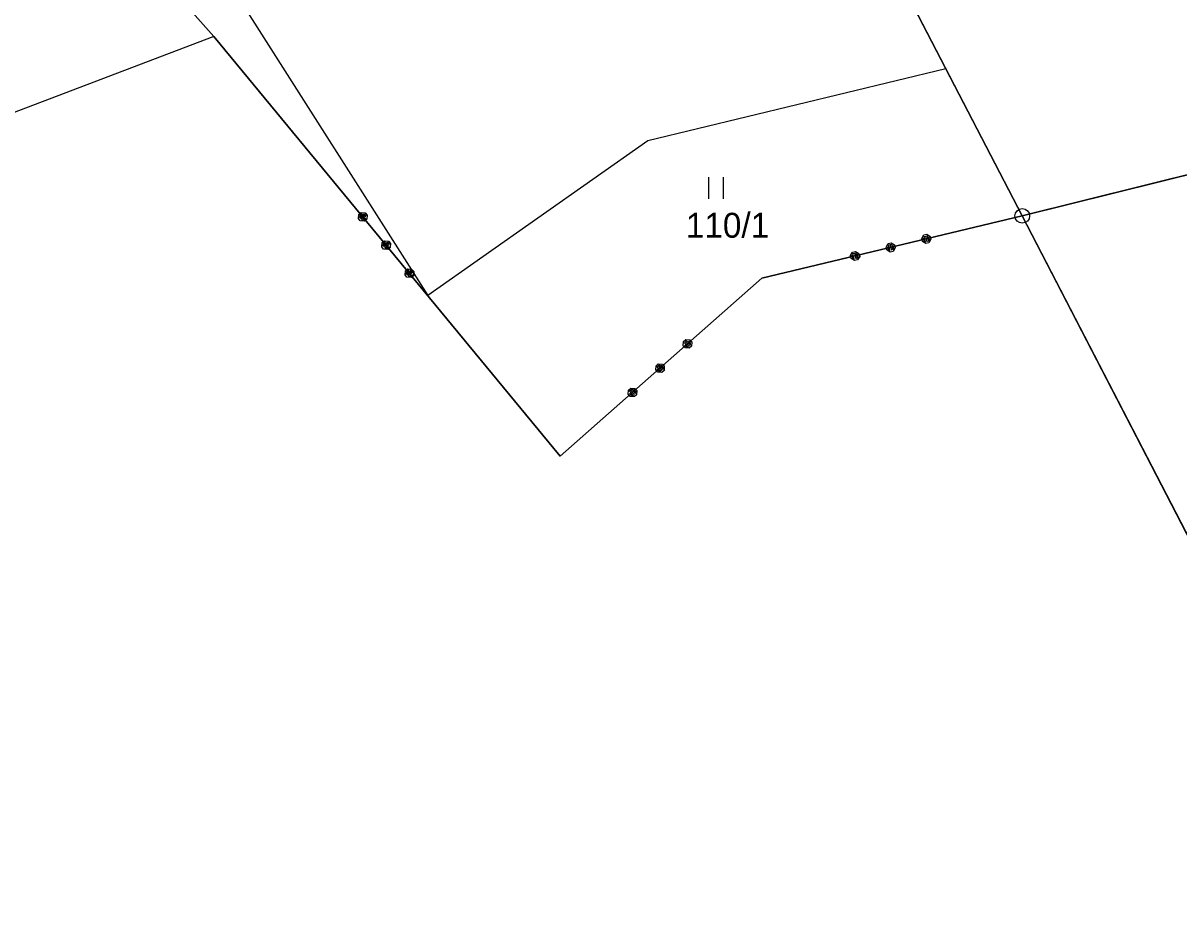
# Model space of a CAD drawing. Extents: x -866656 to -858817, y -1041816 to -1038653.
# Drawn here: x -865090.2 to -865011.3, y -1040747.1 to -1040686 of the extents above; entities that cross this region are included whole.
import ezdxf

# ---------------------------------------------------------------- set-up
doc = ezdxf.new("R2010")
doc.units = 0
for name, color, linetype in [('SZDC', 7, 'Continuous'), ('Vrstva 1', 7, 'Continuous'), ('Vrstva 3', 7, 'Continuous'), ('Vrstva 53', 7, 'Continuous')]:
    doc.layers.add(name, color=color, linetype=linetype)

msp = doc.modelspace()

# ---------------------------------------------------------------- linework, layer by layer
at = {"layer": 'SZDC'}
for points in [[(-865001.396, -1040539.962), (-864993.688, -1040579.203), (-864996.501, -1040608.857), (-865002.06, -1040629.39), (-864985.688, -1040660.423), (-864988.738, -1040690.926), (-865021.96, -1040699.19), (-865027.168, -1040689.139), (-865033.06, -1040677.767), (-865026.63, -1040662), (-865024.654, -1040657.157), (-865013.46, -1040629.71), (-865015.641, -1040623.593), (-865021.207, -1040607.979), (-865022.973, -1040591.404), (-865024.6, -1040576.14), (-865021.44, -1040540.27)], [(-864972.331, -1040948.544), (-864965.463, -1040904.572), (-864985, -1040866.09), (-864987.66, -1040820.56), (-865008.38, -1040725.45), (-865021.96, -1040699.19), (-864988.738, -1040690.926), (-864994.191, -1040709.967), (-864984.36, -1040712.09), (-864979.245, -1040734.883), (-864978.161, -1040739.712), (-864978.755, -1040767.78), (-864956.64, -1040823.78), (-864971.416, -1040839.192), (-864953.61, -1040862.72), (-864958.96, -1040864.07), (-864953.81, -1040886.99), (-864953.18, -1040911.04), (-864934.86, -1040933.14), (-864931.196, -1040972.036)]]:
    msp.add_lwpolyline(points, dxfattribs=at)
at = {"layer": 'Vrstva 1'}
for p, q in [((-865080.1, -1040677.003), (-865062.538, -1040704.629)), ((-865033.06, -1040677.767), (-865021.96, -1040699.19)), ((-865077.15, -1040686.93), (-865106.09, -1040697.94)), ((-865027.168, -1040689.139), (-865047.517, -1040694.061)), ((-865047.517, -1040694.061), (-865062.538, -1040704.629)), ((-865043.383, -1040696.532), (-865043.383, -1040698.032)), ((-865042.383, -1040696.532), (-865042.383, -1040698.032)), ((-865021.96, -1040699.19), (-865008.38, -1040725.45))]:
    msp.add_line(p, q, dxfattribs=at)
for radius in [0.5, 0.01]:
    msp.add_circle((-865021.96, -1040699.19), radius, dxfattribs=at)
at = {"layer": 'Vrstva 3'}
for p, q in [((-865084.06, -1040679.12), (-865077.15, -1040686.93)), ((-865077.15, -1040686.93), (-865084.06, -1040679.12)), ((-865077.15, -1040686.93), (-865053.49, -1040715.59)), ((-865053.49, -1040715.59), (-865077.15, -1040686.93)), ((-865021.96, -1040699.19), (-864988.738, -1040690.926)), ((-864988.738, -1040690.926), (-865021.96, -1040699.19)), ((-865067.27, -1040699.368), (-865067.243, -1040699.087)), ((-865067.27, -1040699.368), (-865067.243, -1040699.087)), ((-865067.142, -1040699.523), (-865067.27, -1040699.368)), ((-865067.142, -1040699.523), (-865067.27, -1040699.368)), ((-865067.243, -1040699.087), (-865067.089, -1040698.959)), ((-865067.243, -1040699.087), (-865067.089, -1040698.959)), ((-865067.193, -1040699.305), (-865066.884, -1040699.05)), ((-865067.193, -1040699.305), (-865066.884, -1040699.05)), ((-865067.179, -1040699.164), (-865067.193, -1040699.305)), ((-865067.179, -1040699.164), (-865067.193, -1040699.305)), ((-865067.025, -1040699.037), (-865067.179, -1040699.164)), ((-865067.025, -1040699.037), (-865067.179, -1040699.164)), ((-865066.861, -1040699.549), (-865067.142, -1040699.523)), ((-865066.861, -1040699.549), (-865067.142, -1040699.523)), ((-865066.821, -1040699.127), (-865067.129, -1040699.382)), ((-865066.821, -1040699.127), (-865067.129, -1040699.382)), ((-865067.089, -1040698.959), (-865066.807, -1040698.986)), ((-865067.089, -1040698.959), (-865066.807, -1040698.986)), ((-865066.757, -1040699.204), (-865067.065, -1040699.459)), ((-865066.757, -1040699.204), (-865067.065, -1040699.459)), ((-865067.065, -1040699.459), (-865066.925, -1040699.472)), ((-865067.065, -1040699.459), (-865066.925, -1040699.472)), ((-865066.925, -1040699.472), (-865066.77, -1040699.345)), ((-865066.925, -1040699.472), (-865066.77, -1040699.345)), ((-865066.884, -1040699.05), (-865066.757, -1040699.204)), ((-865066.884, -1040699.05), (-865066.757, -1040699.204)), ((-865066.707, -1040699.422), (-865066.861, -1040699.549)), ((-865066.707, -1040699.422), (-865066.861, -1040699.549)), ((-865066.807, -1040698.986), (-865066.68, -1040699.141)), ((-865066.807, -1040698.986), (-865066.68, -1040699.141)), ((-865066.68, -1040699.141), (-865066.707, -1040699.422)), ((-865066.68, -1040699.141), (-865066.707, -1040699.422)), ((-865039.73, -1040703.45), (-865021.96, -1040699.19)), ((-865021.96, -1040699.19), (-865039.73, -1040703.45)), ((-865028.826, -1040700.733), (-865028.678, -1040700.492)), ((-865028.826, -1040700.733), (-865028.678, -1040700.492)), ((-865028.678, -1040700.492), (-865028.483, -1040700.445)), ((-865028.678, -1040700.492), (-865028.483, -1040700.445)), ((-865028.483, -1040700.445), (-865028.242, -1040700.593)), ((-865028.483, -1040700.445), (-865028.242, -1040700.593)), ((-865065.678, -1040701.296), (-865065.651, -1040701.015)), ((-865065.678, -1040701.296), (-865065.651, -1040701.015)), ((-865065.651, -1040701.015), (-865065.497, -1040700.887)), ((-865065.651, -1040701.015), (-865065.497, -1040700.887)), ((-865065.601, -1040701.233), (-865065.293, -1040700.978)), ((-865065.601, -1040701.233), (-865065.293, -1040700.978)), ((-865065.588, -1040701.092), (-865065.601, -1040701.233)), ((-865065.588, -1040701.092), (-865065.601, -1040701.233)), ((-865065.433, -1040700.964), (-865065.588, -1040701.092)), ((-865065.433, -1040700.964), (-865065.588, -1040701.092)), ((-865065.229, -1040701.055), (-865065.537, -1040701.31)), ((-865065.229, -1040701.055), (-865065.537, -1040701.31)), ((-865065.497, -1040700.887), (-865065.215, -1040700.914)), ((-865065.497, -1040700.887), (-865065.215, -1040700.914)), ((-865065.165, -1040701.132), (-865065.474, -1040701.387)), ((-865065.165, -1040701.132), (-865065.474, -1040701.387)), ((-865065.333, -1040701.4), (-865065.179, -1040701.273)), ((-865065.333, -1040701.4), (-865065.179, -1040701.273)), ((-865065.293, -1040700.978), (-865065.165, -1040701.132)), ((-865065.293, -1040700.978), (-865065.165, -1040701.132)), ((-865065.215, -1040700.914), (-865065.088, -1040701.069)), ((-865065.215, -1040700.914), (-865065.088, -1040701.069)), ((-865065.088, -1040701.069), (-865065.115, -1040701.35)), ((-865065.088, -1040701.069), (-865065.115, -1040701.35)), ((-865031.257, -1040701.316), (-865031.109, -1040701.074)), ((-865031.257, -1040701.316), (-865031.109, -1040701.074)), ((-865031.16, -1040701.292), (-865031.113, -1040701.487)), ((-865031.16, -1040701.292), (-865031.113, -1040701.487)), ((-865031.109, -1040701.074), (-865030.914, -1040701.028)), ((-865031.109, -1040701.074), (-865030.914, -1040701.028)), ((-865031.086, -1040701.172), (-865030.891, -1040701.125)), ((-865031.086, -1040701.172), (-865030.891, -1040701.125)), ((-865030.992, -1040701.561), (-865031.086, -1040701.172)), ((-865030.992, -1040701.561), (-865031.086, -1040701.172)), ((-865030.988, -1040701.148), (-865030.895, -1040701.537)), ((-865030.988, -1040701.148), (-865030.895, -1040701.537)), ((-865030.914, -1040701.028), (-865030.673, -1040701.176)), ((-865030.914, -1040701.028), (-865030.673, -1040701.176)), ((-865030.891, -1040701.125), (-865030.798, -1040701.514)), ((-865030.891, -1040701.125), (-865030.798, -1040701.514)), ((-865030.724, -1040701.393), (-865030.771, -1040701.199)), ((-865030.724, -1040701.393), (-865030.771, -1040701.199)), ((-865030.673, -1040701.176), (-865030.627, -1040701.37)), ((-865030.673, -1040701.176), (-865030.627, -1040701.37)), ((-865028.779, -1040700.927), (-865028.826, -1040700.733)), ((-865028.779, -1040700.927), (-865028.826, -1040700.733)), ((-865028.538, -1040701.075), (-865028.779, -1040700.927)), ((-865028.538, -1040701.075), (-865028.779, -1040700.927)), ((-865028.728, -1040700.709), (-865028.682, -1040700.904)), ((-865028.728, -1040700.709), (-865028.682, -1040700.904)), ((-865028.682, -1040700.904), (-865028.561, -1040700.978)), ((-865028.682, -1040700.904), (-865028.561, -1040700.978)), ((-865028.655, -1040700.589), (-865028.46, -1040700.542)), ((-865028.655, -1040700.589), (-865028.46, -1040700.542)), ((-865028.561, -1040700.978), (-865028.655, -1040700.589)), ((-865028.561, -1040700.978), (-865028.655, -1040700.589)), ((-865028.557, -1040700.566), (-865028.464, -1040700.955)), ((-865028.557, -1040700.566), (-865028.464, -1040700.955)), ((-865028.343, -1040701.028), (-865028.538, -1040701.075)), ((-865028.343, -1040701.028), (-865028.538, -1040701.075)), ((-865028.46, -1040700.542), (-865028.367, -1040700.931)), ((-865028.46, -1040700.542), (-865028.367, -1040700.931)), ((-865028.367, -1040700.931), (-865028.293, -1040700.811)), ((-865028.367, -1040700.931), (-865028.293, -1040700.811)), ((-865028.196, -1040700.787), (-865028.343, -1040701.028)), ((-865028.196, -1040700.787), (-865028.343, -1040701.028)), ((-865028.293, -1040700.811), (-865028.339, -1040700.616)), ((-865028.293, -1040700.811), (-865028.339, -1040700.616)), ((-865028.242, -1040700.593), (-865028.196, -1040700.787)), ((-865028.242, -1040700.593), (-865028.196, -1040700.787)), ((-865065.551, -1040701.45), (-865065.678, -1040701.296)), ((-865065.551, -1040701.45), (-865065.678, -1040701.296)), ((-865065.269, -1040701.477), (-865065.551, -1040701.45)), ((-865065.269, -1040701.477), (-865065.551, -1040701.45)), ((-865065.474, -1040701.387), (-865065.333, -1040701.4)), ((-865065.474, -1040701.387), (-865065.333, -1040701.4)), ((-865065.115, -1040701.35), (-865065.269, -1040701.477)), ((-865065.115, -1040701.35), (-865065.269, -1040701.477)), ((-865033.688, -1040701.898), (-865033.54, -1040701.657)), ((-865033.688, -1040701.898), (-865033.54, -1040701.657)), ((-865033.641, -1040702.093), (-865033.688, -1040701.898)), ((-865033.641, -1040702.093), (-865033.688, -1040701.898)), ((-865033.591, -1040701.875), (-865033.544, -1040702.07)), ((-865033.591, -1040701.875), (-865033.544, -1040702.07)), ((-865033.544, -1040702.07), (-865033.423, -1040702.143)), ((-865033.544, -1040702.07), (-865033.423, -1040702.143)), ((-865033.54, -1040701.657), (-865033.346, -1040701.611)), ((-865033.54, -1040701.657), (-865033.346, -1040701.611)), ((-865033.517, -1040701.754), (-865033.322, -1040701.708)), ((-865033.517, -1040701.754), (-865033.322, -1040701.708)), ((-865033.423, -1040702.143), (-865033.517, -1040701.754)), ((-865033.423, -1040702.143), (-865033.517, -1040701.754)), ((-865033.419, -1040701.731), (-865033.326, -1040702.12)), ((-865033.419, -1040701.731), (-865033.326, -1040702.12)), ((-865033.346, -1040701.611), (-865033.104, -1040701.758)), ((-865033.346, -1040701.611), (-865033.104, -1040701.758)), ((-865033.322, -1040701.708), (-865033.229, -1040702.097)), ((-865033.322, -1040701.708), (-865033.229, -1040702.097)), ((-865033.229, -1040702.097), (-865033.155, -1040701.976)), ((-865033.229, -1040702.097), (-865033.155, -1040701.976)), ((-865033.058, -1040701.953), (-865033.206, -1040702.194)), ((-865033.058, -1040701.953), (-865033.206, -1040702.194)), ((-865033.155, -1040701.976), (-865033.202, -1040701.782)), ((-865033.155, -1040701.976), (-865033.202, -1040701.782)), ((-865033.104, -1040701.758), (-865033.058, -1040701.953)), ((-865033.104, -1040701.758), (-865033.058, -1040701.953)), ((-865031.21, -1040701.51), (-865031.257, -1040701.316)), ((-865031.21, -1040701.51), (-865031.257, -1040701.316)), ((-865030.969, -1040701.658), (-865031.21, -1040701.51)), ((-865030.969, -1040701.658), (-865031.21, -1040701.51)), ((-865031.113, -1040701.487), (-865030.992, -1040701.561)), ((-865031.113, -1040701.487), (-865030.992, -1040701.561)), ((-865030.775, -1040701.611), (-865030.969, -1040701.658)), ((-865030.775, -1040701.611), (-865030.969, -1040701.658)), ((-865030.798, -1040701.514), (-865030.724, -1040701.393)), ((-865030.798, -1040701.514), (-865030.724, -1040701.393)), ((-865030.627, -1040701.37), (-865030.775, -1040701.611)), ((-865030.627, -1040701.37), (-865030.775, -1040701.611)), ((-865064.06, -1040702.943), (-865063.905, -1040702.815)), ((-865064.06, -1040702.943), (-865063.905, -1040702.815)), ((-865063.905, -1040702.815), (-865063.624, -1040702.842)), ((-865063.905, -1040702.815), (-865063.624, -1040702.842)), ((-865063.624, -1040702.842), (-865063.497, -1040702.996)), ((-865063.624, -1040702.842), (-865063.497, -1040702.996)), ((-865033.4, -1040702.241), (-865033.641, -1040702.093)), ((-865033.4, -1040702.241), (-865033.641, -1040702.093)), ((-865033.206, -1040702.194), (-865033.4, -1040702.241)), ((-865033.206, -1040702.194), (-865033.4, -1040702.241)), ((-865064.087, -1040703.224), (-865064.06, -1040702.943)), ((-865064.087, -1040703.224), (-865064.06, -1040702.943)), ((-865063.959, -1040703.378), (-865064.087, -1040703.224)), ((-865063.959, -1040703.378), (-865064.087, -1040703.224)), ((-865064.009, -1040703.161), (-865063.701, -1040702.906)), ((-865064.009, -1040703.161), (-865063.701, -1040702.906)), ((-865063.996, -1040703.02), (-865064.009, -1040703.161)), ((-865063.996, -1040703.02), (-865064.009, -1040703.161)), ((-865063.842, -1040702.892), (-865063.996, -1040703.02)), ((-865063.842, -1040702.892), (-865063.996, -1040703.02)), ((-865063.678, -1040703.405), (-865063.959, -1040703.378)), ((-865063.678, -1040703.405), (-865063.959, -1040703.378)), ((-865063.637, -1040702.983), (-865063.946, -1040703.238)), ((-865063.637, -1040702.983), (-865063.946, -1040703.238)), ((-865063.574, -1040703.06), (-865063.882, -1040703.315)), ((-865063.574, -1040703.06), (-865063.882, -1040703.315)), ((-865063.882, -1040703.315), (-865063.741, -1040703.328)), ((-865063.882, -1040703.315), (-865063.741, -1040703.328)), ((-865063.741, -1040703.328), (-865063.587, -1040703.201)), ((-865063.741, -1040703.328), (-865063.587, -1040703.201)), ((-865063.701, -1040702.906), (-865063.574, -1040703.06)), ((-865063.701, -1040702.906), (-865063.574, -1040703.06)), ((-865063.523, -1040703.278), (-865063.678, -1040703.405)), ((-865063.523, -1040703.278), (-865063.678, -1040703.405)), ((-865063.497, -1040702.996), (-865063.523, -1040703.278)), ((-865063.497, -1040702.996), (-865063.523, -1040703.278)), ((-865053.49, -1040715.59), (-865039.73, -1040703.45)), ((-865039.73, -1040703.45), (-865053.49, -1040715.59)), ((-865045.101, -1040708.055), (-865045.083, -1040707.773)), ((-865045.101, -1040708.055), (-865045.083, -1040707.773)), ((-865044.969, -1040708.205), (-865045.101, -1040708.055)), ((-865044.969, -1040708.205), (-865045.101, -1040708.055)), ((-865045.083, -1040707.773), (-865044.933, -1040707.641)), ((-865045.083, -1040707.773), (-865044.933, -1040707.641)), ((-865045.026, -1040707.989), (-865044.894, -1040708.139)), ((-865045.026, -1040707.989), (-865044.894, -1040708.139)), ((-865045.017, -1040707.848), (-865044.867, -1040707.716)), ((-865045.017, -1040707.848), (-865044.867, -1040707.716)), ((-865044.752, -1040708.148), (-865045.017, -1040707.848)), ((-865044.752, -1040708.148), (-865045.017, -1040707.848)), ((-865044.686, -1040708.223), (-865044.969, -1040708.205)), ((-865044.686, -1040708.223), (-865044.969, -1040708.205)), ((-865044.942, -1040707.782), (-865044.678, -1040708.082)), ((-865044.942, -1040707.782), (-865044.678, -1040708.082)), ((-865044.933, -1040707.641), (-865044.651, -1040707.658)), ((-865044.933, -1040707.641), (-865044.651, -1040707.658)), ((-865044.894, -1040708.139), (-865044.752, -1040708.148)), ((-865044.894, -1040708.139), (-865044.752, -1040708.148)), ((-865044.867, -1040707.716), (-865044.603, -1040708.016)), ((-865044.867, -1040707.716), (-865044.603, -1040708.016)), ((-865044.594, -1040707.874), (-865044.726, -1040707.724)), ((-865044.594, -1040707.874), (-865044.726, -1040707.724)), ((-865044.536, -1040708.091), (-865044.686, -1040708.223)), ((-865044.536, -1040708.091), (-865044.686, -1040708.223)), ((-865044.651, -1040707.658), (-865044.519, -1040707.808)), ((-865044.651, -1040707.658), (-865044.519, -1040707.808)), ((-865044.603, -1040708.016), (-865044.594, -1040707.874)), ((-865044.603, -1040708.016), (-865044.594, -1040707.874)), ((-865044.519, -1040707.808), (-865044.536, -1040708.091)), ((-865044.519, -1040707.808), (-865044.536, -1040708.091)), ((-865046.976, -1040709.709), (-865046.958, -1040709.427)), ((-865046.976, -1040709.709), (-865046.958, -1040709.427)), ((-865046.843, -1040709.859), (-865046.976, -1040709.709)), ((-865046.843, -1040709.859), (-865046.976, -1040709.709)), ((-865046.958, -1040709.427), (-865046.808, -1040709.295)), ((-865046.958, -1040709.427), (-865046.808, -1040709.295)), ((-865046.901, -1040709.643), (-865046.768, -1040709.793)), ((-865046.901, -1040709.643), (-865046.768, -1040709.793)), ((-865046.892, -1040709.502), (-865046.742, -1040709.37)), ((-865046.892, -1040709.502), (-865046.742, -1040709.37)), ((-865046.627, -1040709.802), (-865046.892, -1040709.502)), ((-865046.627, -1040709.802), (-865046.892, -1040709.502)), ((-865046.561, -1040709.877), (-865046.843, -1040709.859)), ((-865046.561, -1040709.877), (-865046.843, -1040709.859)), ((-865046.817, -1040709.436), (-865046.552, -1040709.736)), ((-865046.817, -1040709.436), (-865046.552, -1040709.736)), ((-865046.808, -1040709.295), (-865046.526, -1040709.312)), ((-865046.808, -1040709.295), (-865046.526, -1040709.312)), ((-865046.768, -1040709.793), (-865046.627, -1040709.802)), ((-865046.768, -1040709.793), (-865046.627, -1040709.802)), ((-865046.742, -1040709.37), (-865046.477, -1040709.669)), ((-865046.742, -1040709.37), (-865046.477, -1040709.669)), ((-865046.468, -1040709.528), (-865046.601, -1040709.378)), ((-865046.468, -1040709.528), (-865046.601, -1040709.378)), ((-865046.411, -1040709.744), (-865046.561, -1040709.877)), ((-865046.411, -1040709.744), (-865046.561, -1040709.877)), ((-865046.526, -1040709.312), (-865046.393, -1040709.462)), ((-865046.526, -1040709.312), (-865046.393, -1040709.462)), ((-865046.477, -1040709.669), (-865046.468, -1040709.528)), ((-865046.477, -1040709.669), (-865046.468, -1040709.528)), ((-865046.393, -1040709.462), (-865046.411, -1040709.744)), ((-865046.393, -1040709.462), (-865046.411, -1040709.744)), ((-865048.85, -1040711.363), (-865048.833, -1040711.081)), ((-865048.85, -1040711.363), (-865048.833, -1040711.081)), ((-865048.718, -1040711.513), (-865048.85, -1040711.363)), ((-865048.718, -1040711.513), (-865048.85, -1040711.363)), ((-865048.833, -1040711.081), (-865048.683, -1040710.949)), ((-865048.833, -1040711.081), (-865048.683, -1040710.949)), ((-865048.775, -1040711.297), (-865048.643, -1040711.447)), ((-865048.775, -1040711.297), (-865048.643, -1040711.447)), ((-865048.766, -1040711.156), (-865048.617, -1040711.024)), ((-865048.766, -1040711.156), (-865048.617, -1040711.024)), ((-865048.502, -1040711.456), (-865048.766, -1040711.156)), ((-865048.502, -1040711.456), (-865048.766, -1040711.156)), ((-865048.436, -1040711.531), (-865048.718, -1040711.513)), ((-865048.436, -1040711.531), (-865048.718, -1040711.513)), ((-865048.691, -1040711.09), (-865048.427, -1040711.39)), ((-865048.691, -1040711.09), (-865048.427, -1040711.39)), ((-865048.683, -1040710.949), (-865048.4, -1040710.966)), ((-865048.683, -1040710.949), (-865048.4, -1040710.966)), ((-865048.643, -1040711.447), (-865048.502, -1040711.456)), ((-865048.643, -1040711.447), (-865048.502, -1040711.456)), ((-865048.617, -1040711.024), (-865048.352, -1040711.323)), ((-865048.617, -1040711.024), (-865048.352, -1040711.323)), ((-865048.343, -1040711.182), (-865048.475, -1040711.032)), ((-865048.343, -1040711.182), (-865048.475, -1040711.032)), ((-865048.286, -1040711.398), (-865048.436, -1040711.531)), ((-865048.286, -1040711.398), (-865048.436, -1040711.531)), ((-865048.4, -1040710.966), (-865048.268, -1040711.116)), ((-865048.4, -1040710.966), (-865048.268, -1040711.116)), ((-865048.352, -1040711.323), (-865048.343, -1040711.182)), ((-865048.352, -1040711.323), (-865048.343, -1040711.182)), ((-865048.268, -1040711.116), (-865048.286, -1040711.398)), ((-865048.268, -1040711.116), (-865048.286, -1040711.398))]:
    msp.add_line(p, q, dxfattribs=at)
at = {"layer": 'Vrstva 53'}
for points in [[(-865021.96, -1040699.19), (-865027.168, -1040689.139), (-865033.06, -1040677.767), (-865026.63, -1040662), (-865024.654, -1040657.157), (-865013.46, -1040629.71), (-865015.641, -1040623.593), (-865021.207, -1040607.979), (-865022.973, -1040591.404), (-865024.6, -1040576.14), (-865021.44, -1040540.27), (-865028.838, -1040510.932), (-865030.491, -1040504.377), (-865038.278, -1040504.827), (-865037.32, -1040476.6), (-865030.762, -1040466.821), (-865030.177, -1040458.81), (-865029.814, -1040453.845), (-865030.983, -1040440.67), (-865031.68, -1040432.82), (-865030.667, -1040387.255), (-865059.89, -1040365.76)], [(-864972.331, -1040948.545), (-864965.463, -1040904.573), (-864985, -1040866.091), (-864987.66, -1040820.561), (-865008.38, -1040725.451), (-865021.96, -1040699.19)]]:
    msp.add_lwpolyline(points, dxfattribs=at)

# ---------------------------------------------------------------- texts
at = {"layer": 'Vrstva 1'}
msp.add_text('110/1', height=1.7, dxfattribs=at).set_placement((-865044.925, -1040700.678))

doc.saveas('drawing.dxf')
